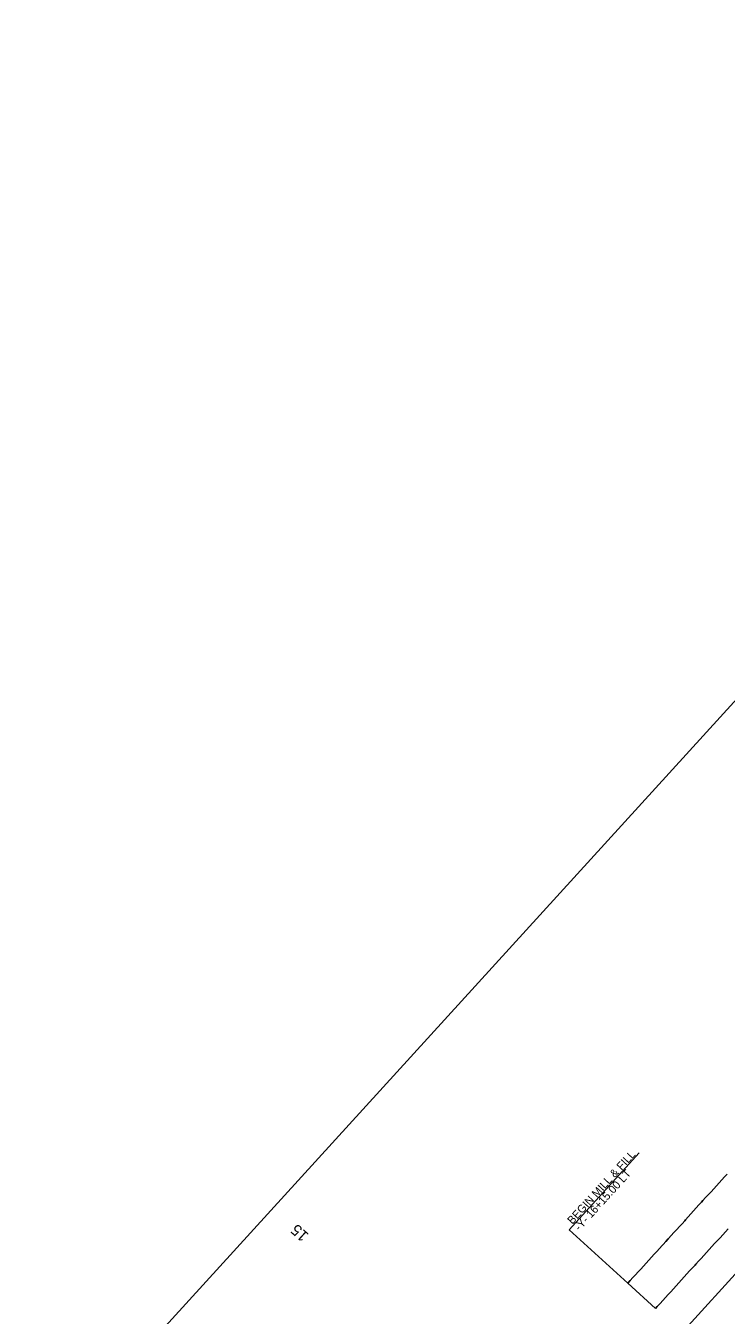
# Model space of a CAD drawing. Extents: x 1807040 to 1808827, y 913493 to 915218.
# Drawn here: x 1807040 to 1807478, y 914236 to 915042 of the extents above; entities that cross this region are included whole.
import ezdxf

# ---------------------------------------------------------------- set-up
doc = ezdxf.new("R2010")
doc.units = 0
for name, color, linetype in [('Prop Dimension', 7, 'Continuous'), ('Prop EOT', 7, 'Continuous'), ('Prop Horizontal Alignment Tick Label', 7, 'Continuous'), ('Scratch_Level_0', 7, 'Continuous'), ('Scratch_Level_1', 7, 'Continuous'), ('Scratch_Level_3', 7, 'Continuous')]:
    doc.layers.add(name, color=color, linetype=linetype)

msp = doc.modelspace()

# ---------------------------------------------------------------- linework, layer by layer
at = {"layer": 'Prop Dimension'}
for p, q in [((1807380.1, 914289.52), (1807423.94, 914337.62)), ((1807416.7, 914256.16), (1807380.1, 914289.52))]:
    msp.add_line(p, q, dxfattribs=at)
at = {"layer": 'Prop EOT'}
msp.add_line((1807416.7, 914256.16), (1807434.01, 914240.38), dxfattribs=at)
for points in [[(1807478.92, 914324.48), (1807477.23, 914322.63), (1807475.55, 914320.79), (1807473.86, 914318.94), (1807472.17, 914317.1), (1807470.48, 914315.26), (1807468.79, 914313.41), (1807467.1, 914311.57), (1807465.41, 914309.73), (1807463.72, 914307.88), (1807462.88, 914306.97), (1807461.21, 914305.11), (1807459.54, 914303.25), (1807457.86, 914301.4), (1807456.19, 914299.54), (1807454.51, 914297.68), (1807452.84, 914295.83), (1807452.35, 914295.29), (1807450.67, 914293.44), (1807448.98, 914291.59), (1807447.3, 914289.74), (1807445.62, 914287.89), (1807443.93, 914286.04), (1807442.25, 914284.2), (1807440.57, 914282.35), (1807438.88, 914280.5), (1807438.28, 914279.84), (1807436.6, 914277.99), (1807434.91, 914276.14), (1807433.23, 914274.29), (1807431.54, 914272.45), (1807429.86, 914270.6), (1807428.17, 914268.75), (1807426.49, 914266.91), (1807424.8, 914265.06), (1807423.29, 914263.41), (1807421.61, 914261.56), (1807419.93, 914259.71), (1807418.25, 914257.86), (1807416.7, 914256.16)], [(1807434.01, 914240.38), (1807435.2, 914241.69), (1807436.88, 914243.54), (1807438.56, 914245.38), (1807440.25, 914247.23), (1807441.93, 914249.08), (1807443.61, 914250.93), (1807445.3, 914252.78), (1807446.98, 914254.62), (1807448.67, 914256.47), (1807450.35, 914258.32), (1807452.03, 914260.17), (1807453.72, 914262.02), (1807455.4, 914263.87), (1807457.08, 914265.71), (1807458.77, 914267.56), (1807459.24, 914268.08), (1807460.93, 914269.93), (1807462.62, 914271.77), (1807464.3, 914273.62), (1807465.99, 914275.46), (1807467.68, 914277.31), (1807469.37, 914279.15), (1807471.05, 914281), (1807472.74, 914282.84), (1807474.43, 914284.68), (1807476.12, 914286.53), (1807477.8, 914288.37), (1807479.49, 914290.22)]]:
    msp.add_lwpolyline(points, dxfattribs=at)
at = {"layer": 'Scratch_Level_0'}
for p, q in [((1807478.92, 914324.48), (1807477.23, 914322.63)), ((1807472.17, 914317.1), (1807470.48, 914315.26)), ((1807461.21, 914305.11), (1807459.54, 914303.25)), ((1807462.88, 914306.97), (1807461.21, 914305.11)), ((1807442.08, 914284.01), (1807440.57, 914282.35)), ((1807447.3, 914289.74), (1807445.62, 914287.89)), ((1807476.12, 914286.53), (1807477.8, 914288.37)), ((1807477.8, 914288.37), (1807479.49, 914290.22)), ((1807434.91, 914276.14), (1807433.23, 914274.29)), ((1807428.17, 914268.75), (1807426.49, 914266.91)), ((1807429.86, 914270.6), (1807428.17, 914268.75)), ((1807431.54, 914272.45), (1807429.86, 914270.6)), ((1807433.23, 914274.29), (1807431.54, 914272.45)), ((1807457.08, 914265.71), (1807458.77, 914267.56)), ((1807460.93, 914269.93), (1807462.62, 914271.77)), ((1807462.62, 914271.77), (1807464.3, 914273.62)), ((1807423.29, 914263.41), (1807421.61, 914261.56)), ((1807424.8, 914265.06), (1807423.29, 914263.41)), ((1807426.49, 914266.91), (1807424.8, 914265.06)), ((1807450.35, 914258.32), (1807452.03, 914260.17)), ((1807452.03, 914260.17), (1807453.72, 914262.02)), ((1807418.25, 914257.86), (1807416.7, 914256.16)), ((1807416.7, 914256.16), (1807434.01, 914240.38)), ((1807445.3, 914252.78), (1807446.98, 914254.62))]:
    msp.add_line(p, q, dxfattribs=at)
for points in [[(1807477.23, 914322.63), (1807475.55, 914320.79), (1807473.86, 914318.94), (1807472.17, 914317.1)], [(1807470.48, 914315.26), (1807468.79, 914313.41), (1807467.1, 914311.57), (1807465.41, 914309.73), (1807463.72, 914307.88), (1807462.88, 914306.97)], [(1807459.54, 914303.25), (1807457.86, 914301.4), (1807456.19, 914299.54), (1807454.51, 914297.68)], [(1807450.67, 914293.44), (1807448.98, 914291.59), (1807447.3, 914289.74)], [(1807454.51, 914297.68), (1807452.84, 914295.83), (1807452.35, 914295.29), (1807450.67, 914293.44)], [(1807445.62, 914287.89), (1807443.93, 914286.04), (1807442.25, 914284.2), (1807442.08, 914284.01)], [(1807472.74, 914282.84), (1807474.43, 914284.68), (1807476.12, 914286.53)], [(1807440.57, 914282.35), (1807438.88, 914280.5), (1807438.28, 914279.84), (1807436.6, 914277.99), (1807434.91, 914276.14)], [(1807464.3, 914273.62), (1807465.99, 914275.46), (1807467.68, 914277.31), (1807469.37, 914279.15), (1807471.05, 914281), (1807472.74, 914282.84)], [(1807458.77, 914267.56), (1807459.24, 914268.08), (1807460.93, 914269.93)], [(1807421.61, 914261.56), (1807419.93, 914259.71), (1807418.25, 914257.86)], [(1807453.72, 914262.02), (1807455.4, 914263.87), (1807457.08, 914265.71)], [(1807438.56, 914245.38), (1807440.25, 914247.23), (1807441.93, 914249.08), (1807443.61, 914250.93), (1807445.3, 914252.78)], [(1807446.98, 914254.62), (1807448.67, 914256.47), (1807450.35, 914258.32)], [(1807434.01, 914240.38), (1807435.2, 914241.69), (1807436.88, 914243.54), (1807438.56, 914245.38)]]:
    msp.add_lwpolyline(points, dxfattribs=at)
at = {"layer": 'Scratch_Level_1'}
msp.add_lwpolyline([(1807040.33, 914133.66), (1807040.33, 914133.66), (1807428.35, 913780.01), (1808256.27, 914688.39), (1807868.25, 915042.04)], close=True, dxfattribs=at)
at = {"layer": 'Scratch_Level_3'}
msp.add_line((1807238.34, 913992.52), (1808046.68, 914879.41), dxfattribs=at)

# ---------------------------------------------------------------- texts
at = {"layer": 'Prop Dimension'}
for s, p in [('BEGIN MILL & FILL', (1807382.1, 914292.68)), ('-Y- 16+15.00 LT', (1807386.53, 914288.64))]:
    msp.add_text(s, height=5, rotation=47.65322, dxfattribs=at).set_placement(p)
at = {"layer": 'Prop Horizontal Alignment Tick Label'}
msp.add_text('15', height=7, rotation=137.65322, dxfattribs=at).set_placement((1807217.69, 914286.68))

doc.saveas('drawing.dxf')
